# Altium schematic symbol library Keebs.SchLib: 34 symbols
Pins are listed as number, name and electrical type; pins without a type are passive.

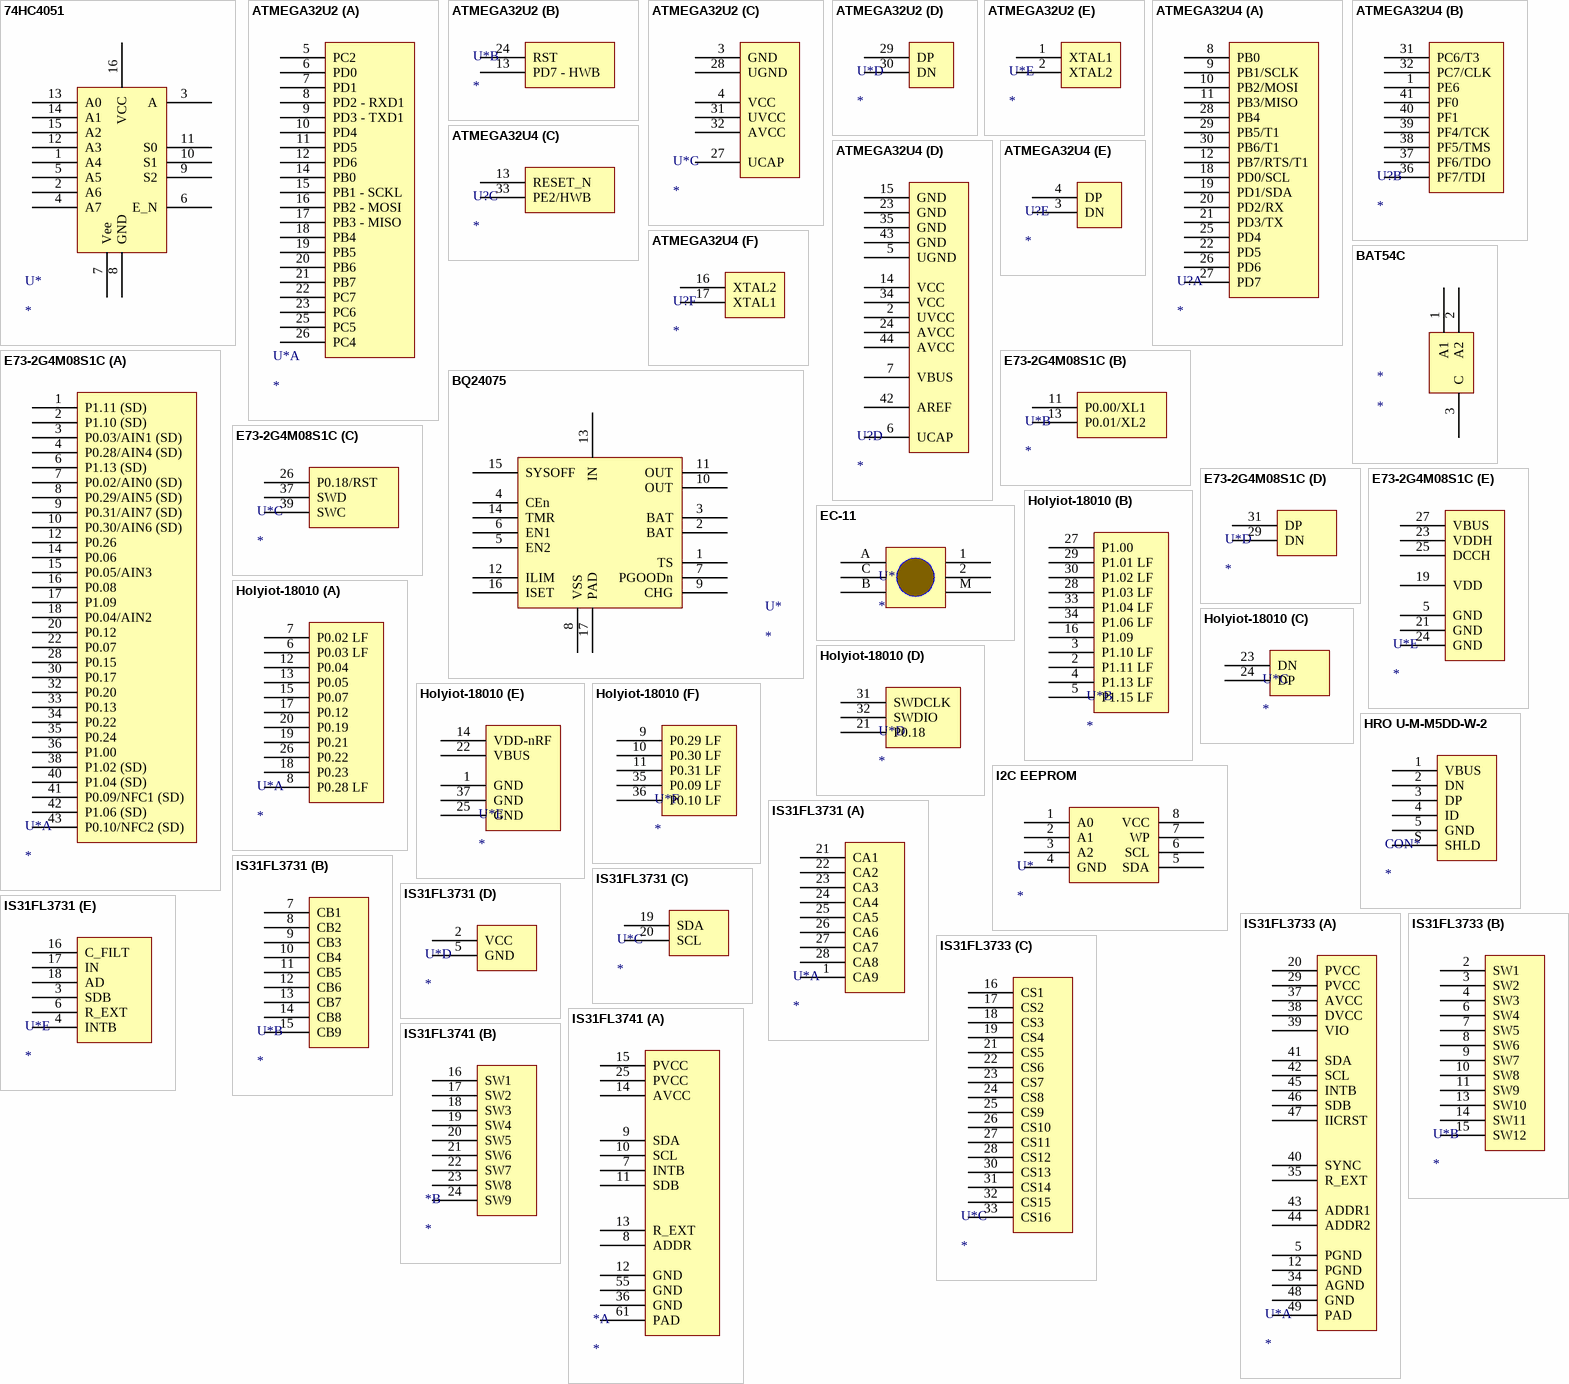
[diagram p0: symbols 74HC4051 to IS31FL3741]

## 74HC4051
designator U*
footprint Texas_Instruments_D_SOIC16
pins: 1 A4, 2 A6, 3 A, 4 A7, 5 A5, 6 E_N, 7 Vee, 8 GND, 9 S2, 10 S1, 11 S0, 12 A3, 13 A0, 14 A1, 15 A2, 16 VCC

## ATMEGA32U2
designator U*
MFG: Microchip Technology; MFGPN: ATMEGA32U2-AUR
footprint ATMEGA32U2-LQFP
part A pins: 5 PC2, 6 PD0, 7 PD1, 8 PD2 - RXD1, 9 PD3 - TXD1, 10 PD4, 11 PD5, 12 PD6, 14 PB0, 15 PB1 - SCKL, 16 PB2 - MOSI, 17 PB3 - MISO, 18 PB4, 19 PB5, 20 PB6, 21 PB7, 22 PC7, 23 PC6, 25 PC5, 26 PC4
part B pins: 13 PD7 - HWB, 24 RST
part C pins: 3 GND, 4 VCC, 27 UCAP, 28 UGND, 31 UVCC, 32 AVCC
part D pins: 29 DP, 30 DN
part E pins: 1 XTAL1, 2 XTAL2

## ATMEGA32U4
designator U?
footprint ATMEGA32U4-COMBO (QFP, 44-Leads, Body 9,95x9,95mm, Pitch 0,80mm, IPC Medium Density)
part A pins: 8 PB0, 9 PB1/SCLK, 10 PB2/MOSI, 11 PB3/MISO, 12 PB7/RTS/T1, 18 PD0/SCL, 19 PD1/SDA, 20 PD2/RX, 21 PD3/TX, 22 PD5, 25 PD4, 26 PD6, 27 PD7, 28 PB4, 29 PB5/T1, 30 PB6/T1
part B pins: 1 PE6, 31 PC6/T3, 32 PC7/CLK, 36 PF7/TDI, 37 PF6/TDO, 38 PF5/TMS, 39 PF4/TCK, 40 PF1, 41 PF0
part C pins: 13 RESET_N, 33 PE2/HWB
part D pins: 2 UVCC, 5 UGND, 6 UCAP, 7 VBUS, 14 VCC, 15 GND, 23 GND, 24 AVCC, 34 VCC, 35 GND, 42 AREF, 43 GND, 44 AVCC
part E pins: 3 DN, 4 DP
part F pins: 16 XTAL2, 17 XTAL1

## BAT54C
designator *
footprint SOT-23-3 (3.3v regulator, used in Windsond S2 proto 1)
pins: 1 A1, 2 A2, 3 C

## BQ24075
designator U*
footprint QFN16 (Generated for BQ24075RGTR)
pins: 1 TS, 2 BAT, 3 BAT, 4 CEn, 5 EN2, 6 EN1, 7 PGOODn, 8 VSS, 9 CHG, 10 OUT, 11 OUT, 12 ILIM, 13 IN, 14 TMR, 15 SYSOFF, 16 ISET, 17 PAD

## E73-2G4M08S1C
designator U*
footprint E73-2G4M08S1C
part A pins: 1 P1.11 (SD), 2 P1.10 (SD), 3 P0.03/AIN1 (SD), 4 P0.28/AIN4 (SD), 6 P1.13 (SD), 7 P0.02/AIN0 (SD), 8 P0.29/AIN5 (SD), 9 P0.31/AIN7 (SD), 10 P0.30/AIN6 (SD), 12 P0.26, 14 P0.06, 15 P0.05/AIN3, 16 P0.08, 17 P1.09, 18 P0.04/AIN2, 20 P0.12, 22 P0.07, 28 P0.15, 30 P0.17, 32 P0.20, 33 P0.13, 34 P0.22, 35 P0.24, 36 P1.00, 38 P1.02 (SD), 40 P1.04 (SD), 41 P0.09/NFC1 (SD), 42 P1.06 (SD), 43 P0.10/NFC2 (SD)
part B pins: 11 P0.00/XL1, 13 P0.01/XL2
part C pins: 26 P0.18/RST, 37 SWD, 39 SWC
part D pins: 29 DN, 31 DP
part E pins: 5 GND, 19 VDD, 21 GND, 23 VDDH, 24 GND, 25 DCCH, 27 VBUS

## EC-11
designator U*
footprint EC11-SMD
footprint EC11-THT
pins: 1, 2, A B, B, C, M

## Holyiot-18010
designator U*
footprint Holyiot-18010 - removed pads (Holyiot long range Nordic nRF52840 chipset BLE module Ceramic Antenna Bluetooth low Energy for Bluetooth mesh)
footprint Holyiot-18010 - outer pads (Holyiot long range Nordic nRF52840 chipset BLE module Ceramic Antenna Bluetooth low Energy for Bluetooth mesh)
part A pins: 6 P0.03 LF, 7 P0.02 LF, 8 P0.28 LF, 12 P0.04, 13 P0.05, 15 P0.07, 17 P0.12, 18 P0.23, 19 P0.21, 20 P0.19, 26 P0.22
part B pins: 2 P1.11 LF, 3 P1.10 LF, 4 P1.13 LF, 5 P1.15 LF, 16 P1.09, 27 P1.00, 28 P1.03 LF, 29 P1.01 LF, 30 P1.02 LF, 33 P1.04 LF, 34 P1.06 LF
part C pins: 23 DN, 24 DP
part D pins: 21 P0.18, 31 SWDCLK, 32 SWDIO
part E pins: 1 GND, 14 VDD-nRF, 22 VBUS, 25 GND, 37 GND
part F pins: 9 P0.29 LF, 10 P0.30 LF, 11 P0.31 LF, 35 P0.09 LF, 36 P0.10 LF

## HRO U-M-M5DD-W-2
designator CON*
footprint HRO U-M-M5DD-W-2
pins: 1 VBUS, 2 DN, 3 DP, 4 ID, 5 GND, S SHLD

## I2C EEPROM
designator U*
footprint SOIC-8 (Based on AT24C256C datasheet)
pins: 1 A0, 2 A1, 3 A2, 4 GND, 5 SDA, 6 SCL, 7 WP, 8 VCC

## IS31FL3731
designator U*
MFGPN: IS31FL3731-SALS2; MFG: ISSI, Integrated Silicon Solution Inc
footprint IS31FL3731 - SOP28
footprint IS31FL3731 - QFN
part A pins: 1 CA9, 21 CA1, 22 CA2, 23 CA3, 24 CA4, 25 CA5, 26 CA6, 27 CA7, 28 CA8
part B pins: 7 CB1, 8 CB2, 9 CB3, 10 CB4, 11 CB5, 12 CB6, 13 CB7, 14 CB8, 15 CB9
part C pins: 19 SDA, 20 SCL
part D pins: 2 VCC, 5 GND
part E pins: 3 SDB, 4 INTB, 6 R_EXT, 16 C_FILT, 17 IN, 18 AD

## IS31FL3733
designator U*
footprint IS31FL3733 - QFP
footprint IS31FL3733 - QFN
part A pins: 5 PGND, 12 PGND, 20 PVCC, 29 PVCC, 34 AGND, 35 R_EXT, 37 AVCC, 38 DVCC, 39 VIO, 40 SYNC, 41 SDA, 42 SCL, 43 ADDR1, 44 ADDR2, 45 INTB, 46 SDB, 47 IICRST, 48 GND, 49 PAD
part B pins: 2 SW1, 3 SW2, 4 SW3, 6 SW4, 7 SW5, 8 SW6, 9 SW7, 10 SW8, 11 SW9, 13 SW10, 14 SW11, 15 SW12
part C pins: 16 CS1, 17 CS2, 18 CS3, 19 CS4, 21 CS5, 22 CS6, 23 CS7, 24 CS8, 25 CS9, 26 CS10, 27 CS11, 28 CS12, 30 CS13, 31 CS14, 32 CS15, 33 CS16

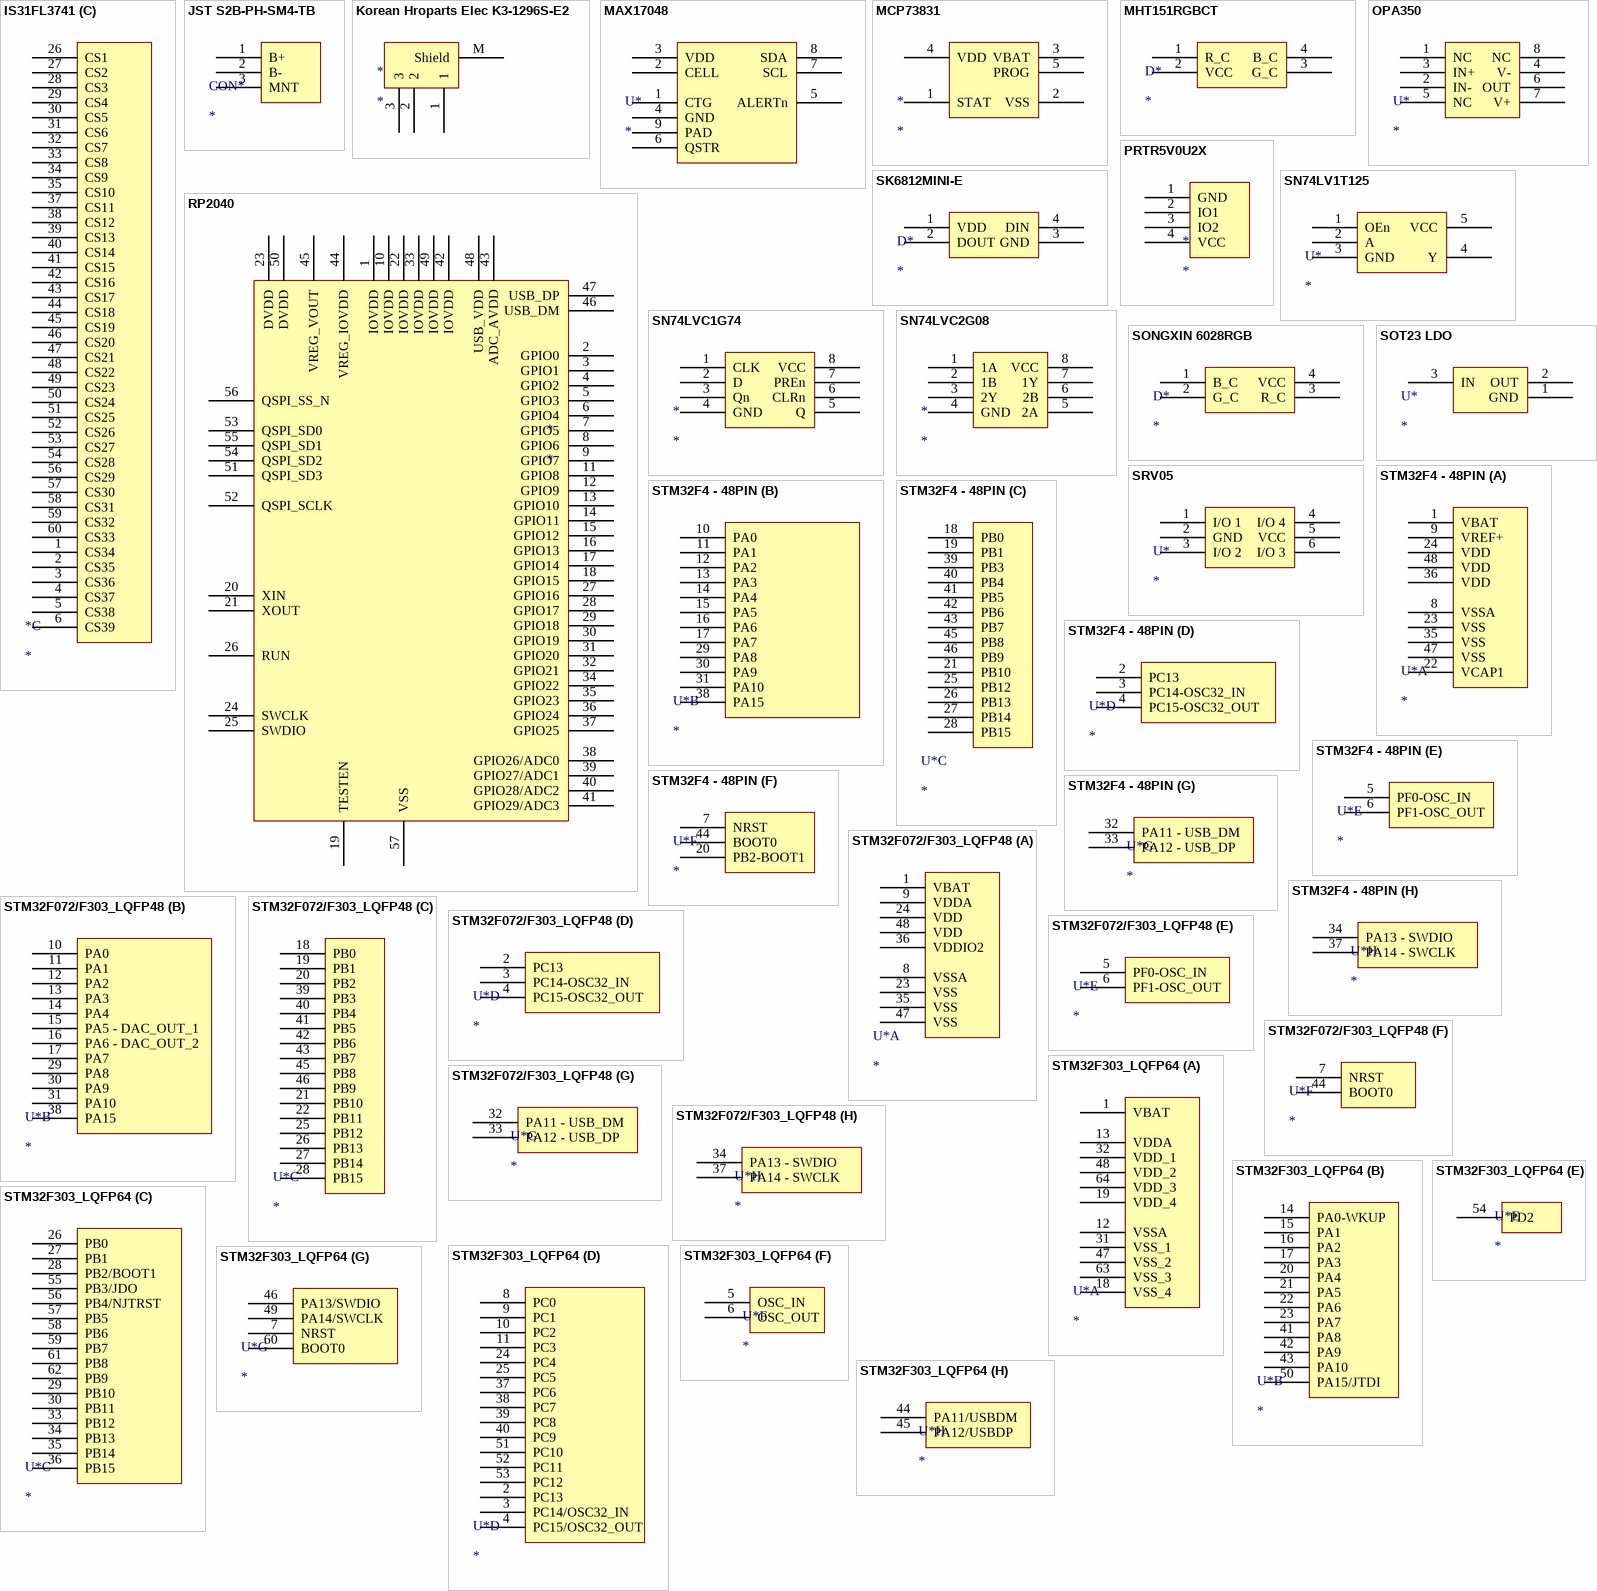
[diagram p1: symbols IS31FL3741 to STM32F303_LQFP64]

## IS31FL3741
designator *
footprint IS31FL3741
part A pins: 7 INTB, 8 ADDR, 9 SDA, 10 SCL, 11 SDB, 12 GND, 13 R_EXT, 14 AVCC, 15 PVCC, 25 PVCC, 36 GND, 55 GND, 61 PAD
part B pins: 16 SW1, 17 SW2, 18 SW3, 19 SW4, 20 SW5, 21 SW6, 22 SW7, 23 SW8, 24 SW9
part C pins: 1 CS34, 2 CS35, 3 CS36, 4 CS37, 5 CS38, 6 CS39, 26 CS1, 27 CS2, 28 CS3, 29 CS4, 30 CS5, 31 CS6, 32 CS7, 33 CS8, 34 CS9, 35 CS10, 37 CS11, 38 CS12, 39 CS13, 40 CS14, 41 CS15, 42 CS16, 43 CS17, 44 CS18, 45 CS19, 46 CS20, 47 CS21, 48 CS22, 49 CS23, 50 CS24, 51 CS25, 52 CS26, 53 CS27, 54 CS28, 56 CS29, 57 CS30, 58 CS31, 59 CS32, 60 CS33

## JST S2B-PH-SM4-TB
designator CON*
footprint JST S2B-PH-SM4-TB
pins: 1 B+, 2 B-, 3 MNT

## Korean Hroparts Elec K3-1296S-E2
designator *
footprint Korean Hroparts Elec K3-1296S-E2
pins: 1, 2, 3, M Shield

## MAX17048
designator U*
footprint 8TDFN (Generated for the MAX17048G+T10)
pins: 1 CTG, 2 CELL, 3 VDD, 4 GND, 5 ALERTn, 6 QSTR, 7 SCL, 8 SDA, 9 PAD

## MCP73831
designator *
footprint SOT-23-5
pins: 1 STAT, 2 VSS, 3 VBAT, 4 VDD, 5 PROG

## MHT151RGBCT
designator D*
footprint MHT151RGBCT (For MHT151RGBCT/E6CC1205RGBC3UDA)
pins: 1 R_C, 2 VCC, 3 G_C, 4 B_C

## OPA350
designator U*
footprint SOIC-8 (Based on AT24C256C datasheet)
pins: 1 NC, 2 IN-, 3 IN+, 4 V-, 5 NC, 6 OUT, 7 V+, 8 NC

## PRTR5V0U2X
designator *
footprint SOT190P237X120-4N (SOT143, 4-Leads, Body 3,00x2,37mm, Pitch 1,90mm, IPC Medium Density)
pins: 1 GND, 2 IO1, 3 IO2, 4 VCC

## RP2040
designator *
footprint RP2040 - QFN56
pins: 1 IOVDD, 2 GPIO0, 3 GPIO1, 4 GPIO2, 5 GPIO3, 6 GPIO4, 7 GPIO5, 8 GPIO6, 9 GPIO7, 10 IOVDD, 11 GPIO8, 12 GPIO9, 13 GPIO10, 14 GPIO11, 15 GPIO12, 16 GPIO13, 17 GPIO14, 18 GPIO15, 19 TESTEN, 20 XIN, 21 XOUT, 22 IOVDD, 23 DVDD, 24 SWCLK, 25 SWDIO, 26 RUN, 27 GPIO16, 28 GPIO17, 29 GPIO18, 30 GPIO19, 31 GPIO20, 32 GPIO21, 33 IOVDD, 34 GPIO22, 35 GPIO23, 36 GPIO24, 37 GPIO25, 38 GPIO26/ADC0, 39 GPIO27/ADC1, 40 GPIO28/ADC2, 41 GPIO29/ADC3, 42 IOVDD, 43 ADC_AVDD, 44 VREG_IOVDD, 45 VREG_VOUT, 46 USB_DM, 47 USB_DP, 48 USB_VDD, 49 IOVDD, 50 DVDD, 51 QSPI_SD3, 52 QSPI_SCLK, 53 QSPI_SD0, 54 QSPI_SD2, 55 QSPI_SD1, 56 QSPI_SS_N, 57 VSS

## SK6812MINI-E
designator D*
footprint SK6812MINI-E
pins: 1 VDD, 2 DOUT, 3 GND, 4 DIN

## SN74LV1T125
designator U*
SN74LV1T125 or SN74LV1T34. Connect OE to GND
footprint SOT-23-5
pins: 1 OEn, 2 A, 3 GND, 4 Y, 5 VCC

## SN74LVC1G74
designator *
footprint VSSOP8 (Dimensions from SN74LVC2G08DCUR)
pins: 1 CLK, 2 D, 3 Qn, 4 GND, 5 Q, 6 CLRn, 7 PREn, 8 VCC

## SN74LVC2G08
designator *
footprint VSSOP8 (Dimensions from SN74LVC2G08DCUR)
pins: 1 1A, 2 1B, 3 2Y, 4 GND, 5 2A, 6 2B, 7 1Y, 8 VCC

## SONGXIN 6028RGB
designator D*
footprint SONGXIN 6028RGB (Common Anode reverse mount LED)
pins: 1 B_C, 2 G_C, 3 R_C, 4 VCC

## SOT23 LDO
designator U*
MRF.Part: XC6206P332MR; LCSC MFG: Torex Semicon; MFG: Texas Instruments; MFGPN: TPS7A0533PDBZ
footprint SOT-23-3 (3.3v regulator, used in Windsond S2 proto 1)
pins: 1 GND, 2 OUT, 3 IN

## SRV05
designator U*
footprint SOT-23-6
pins: 1 I/O 1, 2 GND, 3 I/O 2, 4 I/O 4, 5 VCC, 6 I/O 3

## STM32F4 - 48PIN
designator U*
MFG: STMicroelectronics; MFGPN: STM32F072CBT6TR
footprint STM32 - LQFP48, 7x7mm (LQFP48, 7x7mm)
part A pins: 1 VBAT, 8 VSSA, 9 VREF+, 22 VCAP1, 23 VSS, 24 VDD, 35 VSS, 36 VDD, 47 VSS, 48 VDD
part B pins: 10 PA0, 11 PA1, 12 PA2, 13 PA3, 14 PA4, 15 PA5, 16 PA6, 17 PA7, 29 PA8, 30 PA9, 31 PA10, 38 PA15
part C pins: 18 PB0, 19 PB1, 21 PB10, 25 PB12, 26 PB13, 27 PB14, 28 PB15, 39 PB3, 40 PB4, 41 PB5, 42 PB6, 43 PB7, 45 PB8, 46 PB9
part D pins: 2 PC13, 3 PC14-OSC32_IN, 4 PC15-OSC32_OUT
part E pins: 5 PF0-OSC_IN, 6 PF1-OSC_OUT
part F pins: 7 NRST, 20 PB2-BOOT1, 44 BOOT0
part G pins: 32 PA11 - USB_DM, 33 PA12 - USB_DP
part H pins: 34 PA13 - SWDIO, 37 PA14 - SWCLK

## STM32F072/F303_LQFP48
designator U*
MFG: STMicroelectronics; MFGPN: STM32F072CBT6TR
footprint STM32 - LQFP48, 7x7mm (LQFP48, 7x7mm)
part A pins: 1 VBAT, 8 VSSA, 9 VDDA, 23 VSS, 24 VDD, 35 VSS, 36 VDDIO2, 47 VSS, 48 VDD
part B pins: 10 PA0, 11 PA1, 12 PA2, 13 PA3, 14 PA4, 15 PA5 - DAC_OUT_1, 16 PA6 - DAC_OUT_2, 17 PA7, 29 PA8, 30 PA9, 31 PA10, 38 PA15
part C pins: 18 PB0, 19 PB1, 20 PB2, 21 PB10, 22 PB11, 25 PB12, 26 PB13, 27 PB14, 28 PB15, 39 PB3, 40 PB4, 41 PB5, 42 PB6, 43 PB7, 45 PB8, 46 PB9
part D pins: 2 PC13, 3 PC14-OSC32_IN, 4 PC15-OSC32_OUT
part E pins: 5 PF0-OSC_IN, 6 PF1-OSC_OUT
part F pins: 7 NRST, 44 BOOT0
part G pins: 32 PA11 - USB_DM, 33 PA12 - USB_DP
part H pins: 34 PA13 - SWDIO, 37 PA14 - SWCLK

## STM32F303_LQFP64
designator U*
footprint STM32 - LQFP64, 10x10mm (TSQFP, 64-Leads, Body 10.00x10.00mm, Pitch 0.50mm, IPC Medium Density)
part A pins: 1 VBAT, 12 VSSA, 13 VDDA, 18 VSS_4, 19 VDD_4, 31 VSS_1, 32 VDD_1, 47 VSS_2, 48 VDD_2, 63 VSS_3, 64 VDD_3
part B pins: 14 PA0-WKUP, 15 PA1, 16 PA2, 17 PA3, 20 PA4, 21 PA5, 22 PA6, 23 PA7, 41 PA8, 42 PA9, 43 PA10, 50 PA15/JTDI
part C pins: 26 PB0, 27 PB1, 28 PB2/BOOT1, 29 PB10, 30 PB11, 33 PB12, 34 PB13, 35 PB14, 36 PB15, 55 PB3/JDO, 56 PB4/NJTRST, 57 PB5, 58 PB6, 59 PB7, 61 PB8, 62 PB9
part D pins: 2 PC13, 3 PC14/OSC32_IN, 4 PC15/OSC32_OUT, 8 PC0, 9 PC1, 10 PC2, 11 PC3, 24 PC4, 25 PC5, 37 PC6, 38 PC7, 39 PC8, 40 PC9, 51 PC10, 52 PC11, 53 PC12
part E pins: 54 PD2
part F pins: 5 OSC_IN, 6 OSC_OUT
part G pins: 7 NRST, 46 PA13/SWDIO, 49 PA14/SWCLK, 60 BOOT0
part H pins: 44 PA11/USBDM, 45 PA12/USBDP

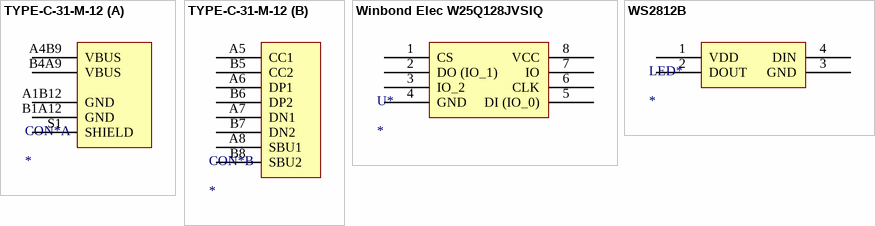
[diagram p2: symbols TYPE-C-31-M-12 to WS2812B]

## TYPE-C-31-M-12
designator CON*
MFG: Korean Hroparts Elec; MFGPN: TYPE-C-31-M-12
footprint TYPE-C-31-M-12
part A pins: A1B12 GND, A4B9 VBUS, B1A12 GND, B4A9 VBUS, S1 SHIELD
part B pins: A5 CC1, A6 DP1, A7 DN1, A8 SBU1, B5 CC2, B6 DP2, B7 DN2, B8 SBU2

## Winbond Elec W25Q128JVSIQ
designator U*
footprint SOIC-8 (Based on AT24C256C datasheet)
pins: 1 CS, 2 DO (IO_1), 3 IO_2, 4 GND, 5 DI (IO_0), 6 CLK, 7 IO, 8 VCC

## WS2812B
designator LED*
MFGPN: WS2812B
footprint WS2812B
pins: 1 VDD, 2 DOUT, 3 GND, 4 DIN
